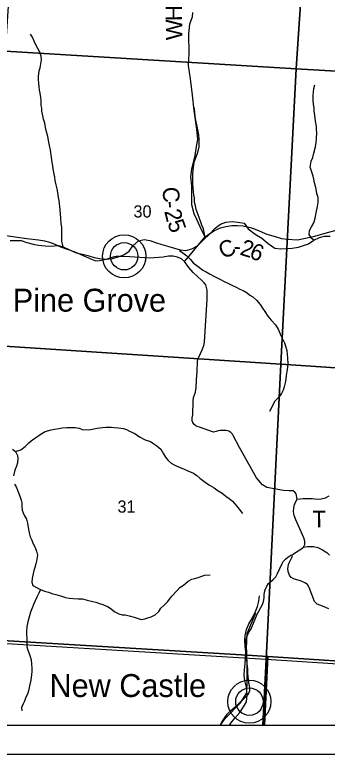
# Model space of a CAD drawing. Extents: x 0 to 34, y 0 to 22.
# Drawn here: x 6.352 to 7.429, y 14 to 16.547 of the extents above; entities that cross this region are included whole.
import ezdxf

# ---------------------------------------------------------------- set-up
doc = ezdxf.new("R2010")
doc.units = 0
for name, color, linetype in [('GM_X_County_Road', 7, 'Continuous'), ('GM_X_County_Road_Text', 7, 'Continuous'), ('GM_X_Minor_River', 7, 'Continuous'), ('GM_X_Rail_Line', 7, 'Continuous'), ('GM_X_Section', 7, 'Continuous'), ('GM_X_Section_Text', 7, 'Continuous'), ('GM_X_State_Route', 7, 'Continuous'), ('GM_X_Township_Road', 7, 'Continuous'), ('GM_X_Township_Road_Text', 7, 'Continuous'), ('GM_X_Unincorporated', 7, 'Continuous'), ('GM_X_Unincorporated_Location', 7, 'Continuous'), ('GM_X_Unincorporated_Text', 7, 'Continuous'), ('SH_Cut_Line', 7, 'Continuous'), ('SH_Data', 7, 'Continuous')]:
    doc.layers.add(name, color=color, linetype=linetype)

msp = doc.modelspace()

# ---------------------------------------------------------------- linework, layer by layer
at = {"layer": 'GM_X_County_Road'}
for points in [[(7.0019, 15.7742), (7.0087, 15.7819), (6.9968, 15.8044), (6.9804, 15.8419), (6.9711, 15.8614), (6.963, 15.8929), (6.963, 15.9563), (6.9594, 15.989), (6.963, 16.0159), (6.9743, 16.0626), (6.9791, 16.0937), (6.9834, 16.118), (6.9795, 16.1533), (6.9708, 16.2175), (6.9647, 16.2703), (6.9586, 16.3266), (6.9517, 16.3722), (6.9539, 16.4139), (6.9528, 16.4808), (6.9564, 16.5157), (6.9645, 16.5396), (6.9662, 16.5551)], [(7.0087, 15.7819), (7.0219, 15.7915), (7.0407, 15.8036), (7.062, 15.813), (7.0797, 15.8184), (7.1006, 15.821), (7.1207, 15.8216), (7.1397, 15.82), (7.1647, 15.8143), (7.1869, 15.8063), (7.2217, 15.7916), (7.2496, 15.7833), (7.2723, 15.7765), (7.2913, 15.7742), (7.327, 15.7714), (7.3551, 15.7777), (7.3867, 15.7844), (7.4221, 15.7954), (7.4604, 15.8049)], [(6.9379, 15.6975), (6.9532, 15.7152), (6.9743, 15.7414), (6.9959, 15.7673), (7.0019, 15.7742)], [(7.4356, 14.5013), (7.4129, 14.5094), (7.3951, 14.5171), (7.3853, 14.5259), (7.3673, 14.5745), (7.3612, 14.5841), (7.3528, 14.5902), (7.3378, 14.5968), (7.3171, 14.6029), (7.3056, 14.6086), (7.2991, 14.6167), (7.2952, 14.6293), (7.2942, 14.6392), (7.2944, 14.646), (7.2962, 14.654), (7.2999, 14.6614), (7.308, 14.6779), (7.31, 14.6832), (7.3092, 14.6869)]]:
    msp.add_lwpolyline(points, dxfattribs=at)
at = {"layer": 'GM_X_Minor_River'}
for points in [[(6.5192, 15.7482), (6.515, 15.767), (6.5146, 15.7822), (6.5146, 15.7917), (6.515, 15.8015), (6.5142, 15.8152), (6.5127, 15.8265), (6.5108, 15.8478), (6.5101, 15.8599), (6.5089, 15.8758), (6.5052, 15.9077), (6.5036, 15.9172), (6.501, 15.935), (6.498, 15.9475), (6.495, 15.9615), (6.4919, 15.976), (6.4904, 15.9873), (6.4882, 15.9987), (6.4851, 16.0169), (6.4833, 16.0268), (6.4806, 16.045), (6.4787, 16.0575), (6.4765, 16.0711), (6.475, 16.0814), (6.4731, 16.0912), (6.4693, 16.1087), (6.4659, 16.128), (6.461, 16.1489), (6.4583, 16.1591), (6.4561, 16.1735), (6.4515, 16.1876), (6.4485, 16.205), (6.4459, 16.2152), (6.4451, 16.2255), (6.4436, 16.235), (6.4429, 16.2528), (6.4421, 16.2623), (6.4398, 16.2774), (6.438, 16.288), (6.4364, 16.299), (6.4353, 16.3112), (6.4338, 16.3229), (6.4338, 16.3351), (6.4361, 16.354), (6.4395, 16.365), (6.4421, 16.3783), (6.4444, 16.392), (6.4436, 16.4041), (6.4387, 16.4185), (6.4316, 16.431), (6.4236, 16.4462), (6.4191, 16.4568), (6.413, 16.4697), (6.4067, 16.4808)], [(7.3831, 15.771), (7.3768, 15.7766), (7.3674, 15.7899), (7.3689, 15.8043), (7.3749, 15.8164), (7.3833, 15.8308), (7.3882, 15.8471), (7.3912, 15.8646), (7.3957, 15.8866), (7.3988, 15.9002), (7.398, 15.9173), (7.3942, 15.9321), (7.3908, 15.9461), (7.389, 15.9567), (7.3856, 15.9685), (7.3829, 15.9814), (7.381, 15.9909), (7.3704, 16.0227), (7.3742, 16.0428), (7.3795, 16.0553), (7.3837, 16.0701), (7.389, 16.0918), (7.3909, 16.1073), (7.3924, 16.1206), (7.3935, 16.1403), (7.3928, 16.1505), (7.392, 16.1619), (7.3894, 16.1805), (7.3882, 16.1911), (7.3867, 16.201), (7.3849, 16.2161), (7.3841, 16.2268), (7.3818, 16.2397), (7.3811, 16.2518), (7.3815, 16.27), (7.3834, 16.2927), (7.3868, 16.3053)], [(7.0095, 15.7782), (7.0067, 15.7909), (7.0026, 15.8095), (6.9977, 15.8228), (6.9935, 15.8327), (6.9887, 15.8452), (6.9834, 15.8619), (6.9781, 15.8763), (6.9755, 15.8892), (6.9714, 15.9021), (6.9714, 15.9162), (6.9692, 15.9272), (6.9681, 15.9382), (6.967, 15.9503), (6.9659, 15.9651), (6.9659, 15.9799), (6.9663, 15.997), (6.9675, 16.0118), (6.9698, 16.0311), (6.9725, 16.0428), (6.9782, 16.0576), (6.982, 16.0701), (6.9855, 16.0815), (6.9878, 16.0928), (6.9878, 16.1046), (6.9882, 16.1194), (6.9871, 16.1342), (6.98, 16.168), (6.9767, 16.1847), (6.9744, 16.1979), (6.9726, 16.2105), (6.9715, 16.2234), (6.9707, 16.2283)], [(6.3364, 15.7701), (6.3542, 15.7697), (6.3743, 15.7693), (6.3939, 15.7624), (6.4159, 15.7575), (6.4344, 15.754), (6.4575, 15.751), (6.4772, 15.7506), (6.5018, 15.7524), (6.5192, 15.7482), (6.5385, 15.7387), (6.5642, 15.7277), (6.5858, 15.7227), (6.6043, 15.7181), (6.6262, 15.7116), (6.644, 15.7074), (6.6675, 15.7051), (6.6887, 15.7074), (6.7088, 15.7135), (6.7281, 15.7199), (6.7463, 15.7328), (6.7596, 15.7507), (6.7789, 15.7682), (6.799, 15.7731), (6.8179, 15.7696), (6.838, 15.7632), (6.8592, 15.7559), (6.883, 15.7487), (6.9027, 15.7429), (6.922, 15.7372), (6.942, 15.7357), (6.9628, 15.7414), (6.9825, 15.7509), (7.0027, 15.7714), (7.0232, 15.7919), (7.0429, 15.8124), (7.0618, 15.8261), (7.08, 15.8333), (7.1016, 15.8355), (7.1209, 15.8329), (7.1432, 15.8294), (7.1564, 15.8093), (7.1806, 15.791), (7.2041, 15.778), (7.2264, 15.7598), (7.2487, 15.7434), (7.268, 15.7407), (7.288, 15.7422), (7.3085, 15.743), (7.3301, 15.7464), (7.3482, 15.7521), (7.3653, 15.7585), (7.3831, 15.771), (7.4028, 15.7805), (7.4203, 15.7851), (7.4392, 15.7851)], [(6.922, 15.7372), (6.9198, 15.7357), (6.9323, 15.7274), (6.9455, 15.7164), (6.958, 15.7039), (6.9678, 15.6925), (6.9848, 15.68), (7.0007, 15.6679), (7.012, 15.6618), (7.0264, 15.6535), (7.0404, 15.6459), (7.0589, 15.6365), (7.0763, 15.627), (7.0869, 15.6224), (7.1001, 15.6156), (7.1152, 15.6088), (7.1277, 15.6016), (7.1398, 15.5971), (7.153, 15.5891), (7.1628, 15.5815), (7.173, 15.5758), (7.1855, 15.5637), (7.198, 15.5493), (7.2059, 15.5368), (7.2146, 15.5247), (7.2252, 15.5095), (7.2361, 15.4947), (7.2516, 15.4788), (7.2607, 15.4644), (7.2709, 15.4401), (7.2773, 15.4261), (7.2826, 15.4166), (7.2864, 15.4018), (7.2902, 15.3905), (7.2913, 15.3768), (7.2928, 15.3654), (7.2936, 15.3453), (7.2921, 15.3328), (7.2905, 15.3184), (7.2875, 15.304), (7.2868, 15.2919), (7.2845, 15.2797), (7.2811, 15.2653), (7.2777, 15.2543), (7.2724, 15.2422), (7.2625, 15.2304), (7.2489, 15.2167), (7.23, 15.1805)], [(6.3549, 15.0422), (6.3731, 15.0487), (6.3886, 15.0604), (6.4014, 15.0726), (6.4146, 15.0836), (6.4271, 15.0927), (6.4396, 15.101), (6.4574, 15.1113), (6.4782, 15.1177), (6.4899, 15.1193), (6.5039, 15.1223), (6.5156, 15.1242), (6.5322, 15.1257), (6.5609, 15.1257), (6.5745, 15.1227), (6.5844, 15.1182), (6.6074, 15.117), (6.6192, 15.1193), (6.6369, 15.1231), (6.6543, 15.125), (6.6664, 15.1269), (6.6857, 15.1266), (6.6963, 15.1258), (6.7095, 15.1243), (6.7276, 15.1224), (6.7378, 15.1186), (6.7477, 15.1133), (6.7666, 15.1042), (6.7824, 15.0936), (6.8017, 15.0834), (6.8206, 15.0769), (6.8312, 15.0697), (6.8422, 15.0622), (6.8554, 15.0508), (6.8648, 15.0352), (6.8724, 15.0235), (6.8811, 15.0121), (6.8913, 15.003), (6.9015, 14.997), (6.9189, 14.989), (6.9344, 14.9826), (6.9491, 14.9765), (6.9684, 14.9678), (6.9797, 14.9606), (6.9907, 14.9507), (7.0088, 14.9367), (7.0236, 14.9265), (7.0398, 14.9181), (7.0534, 14.9075), (7.067, 14.8988), (7.0795, 14.8893), (7.0912, 14.881), (7.103, 14.8715), (7.1169, 14.8552), (7.1264, 14.8446), (7.1377, 14.8295)], [(6.3443, 15.0505), (6.3549, 15.0422), (6.3617, 15.0286), (6.3625, 15.0187), (6.3617, 15.0039), (6.3583, 14.9925), (6.353, 14.9781), (6.3477, 14.9591)], [(6.3515, 14.9307), (6.3583, 14.9186), (6.3613, 14.9091), (6.3662, 14.8981), (6.3704, 14.8852), (6.3749, 14.8753), (6.3768, 14.8655), (6.3772, 14.8537), (6.3779, 14.8412), (6.3813, 14.8314), (6.3855, 14.8207), (6.3923, 14.8094), (6.3968, 14.7953), (6.398, 14.7805), (6.4021, 14.7627), (6.4059, 14.7483), (6.4115, 14.7377), (6.4153, 14.7244), (6.4221, 14.7146), (6.4274, 14.6998), (6.4312, 14.6854), (6.4278, 14.6653), (6.4255, 14.6558), (6.421, 14.6436), (6.4176, 14.6323), (6.4149, 14.6163), (6.4119, 14.6049), (6.4115, 14.5932), (6.4149, 14.5811), (6.43, 14.5727), (6.4406, 14.567), (6.4554, 14.5614), (6.4682, 14.5579), (6.4833, 14.553), (6.4935, 14.5504), (6.5105, 14.5454), (6.5268, 14.5401), (6.5397, 14.5379), (6.554, 14.5364), (6.5706, 14.5356), (6.5858, 14.5349), (6.602, 14.5311), (6.6217, 14.5262), (6.6323, 14.5239), (6.644, 14.5197), (6.6557, 14.5159), (6.6716, 14.5084), (6.6848, 14.5008), (6.6973, 14.4905), (6.7116, 14.4833), (6.723, 14.4803), (6.7332, 14.4796), (6.7472, 14.4762), (6.7638, 14.4716), (6.7774, 14.4678), (6.7891, 14.4644), (6.8005, 14.4659)], [(6.8005, 14.4659), (6.8114, 14.4701), (6.8224, 14.4732), (6.8368, 14.4804), (6.8485, 14.4918), (6.856, 14.5031), (6.8674, 14.5138), (6.8783, 14.5251), (6.887, 14.535), (6.8942, 14.5445), (6.912, 14.5642), (6.9214, 14.5741), (6.9339, 14.5828), (6.9506, 14.5961), (6.963, 14.6026), (6.9729, 14.6052), (6.985, 14.609), (6.9967, 14.6136), (7.008, 14.6162), (7.0254, 14.6174)], [(6.4406, 14.567), (6.4395, 14.5655), (6.4357, 14.5549), (6.4289, 14.5405), (6.4168, 14.5162), (6.4134, 14.5067), (6.407, 14.4889), (6.3971, 14.4555), (6.3945, 14.4392), (6.393, 14.4229), (6.3933, 14.4134), (6.3945, 14.3979), (6.3941, 14.3842), (6.3945, 14.3702), (6.3975, 14.3588), (6.402, 14.347), (6.4058, 14.3364), (6.4084, 14.325), (6.4103, 14.3118), (6.4111, 14.2955), (6.4107, 14.2841), (6.4103, 14.2742), (6.408, 14.2552), (6.4046, 14.2405), (6.4024, 14.2298), (6.3993, 14.2181), (6.3959, 14.2063), (6.391, 14.1961), (6.3861, 14.1832), (6.3808, 14.1733), (6.3759, 14.1608), (6.377, 14.1494)], [(7.0927, 14.1), (7.0969, 14.1072), (7.1109, 14.1243), (7.128, 14.1441), (7.1409, 14.1627), (7.1515, 14.1802), (7.1531, 14.2041), (7.1513, 14.2308), (7.1453, 14.2536), (7.1434, 14.2711), (7.1446, 14.2912), (7.1465, 14.3118), (7.1481, 14.3327), (7.1493, 14.3525), (7.1463, 14.3719), (7.146, 14.3913), (7.1464, 14.4088), (7.151, 14.4293), (7.1594, 14.4494), (7.1723, 14.47), (7.1822, 14.4916), (7.1886, 14.5091), (7.1936, 14.5277), (7.1959, 14.5456)]]:
    msp.add_lwpolyline(points, dxfattribs=at)
at = {"layer": 'GM_X_Rail_Line'}
msp.add_lwpolyline([(7.0621, 14.1), (7.0777, 14.123), (7.1304, 14.177), (7.1522, 14.2117), (7.1532, 14.2534), (7.1539, 14.3132), (7.1513, 14.3637), (7.1532, 14.4153), (7.1836, 14.4865)], dxfattribs=at)
at = {"layer": 'GM_X_Section'}
for points in [[(6.388, 17.4386), (7.3907, 17.3751), (7.3221, 16.3607), (6.3205, 16.4222)], [(7.3907, 17.3751), (8.3983, 17.3128), (8.3308, 16.3019), (7.3221, 16.3607)], [(6.3205, 16.4222), (7.3221, 16.3607), (7.27, 15.3432), (6.2624, 15.4089)], [(7.3221, 16.3607), (8.3308, 16.3019), (8.2829, 15.2756), (7.27, 15.3432)], [(7.27, 15.3432), (7.2187, 14.3265), (6.2103, 14.3869), (6.2624, 15.4089)], [(8.2829, 15.2756), (8.2289, 14.2604), (7.2187, 14.3265), (7.27, 15.3432)]]:
    msp.add_lwpolyline(points, close=True, dxfattribs=at)
at = {"layer": 'GM_X_State_Route'}
for points in [[(6.9379, 15.6975), (6.9273, 15.706), (6.9129, 15.7125), (6.8985, 15.7153), (6.8821, 15.7156), (6.8637, 15.7122), (6.8177, 15.7093), (6.749, 15.7139), (6.7119, 15.715), (6.7015, 15.7145), (6.6905, 15.7121), (6.6794, 15.7092), (6.6674, 15.7046), (6.6517, 15.7004), (6.6376, 15.6988), (6.6294, 15.6998), (6.6178, 15.7041), (6.5812, 15.7207), (6.5608, 15.729), (6.5112, 15.7464), (6.4917, 15.7556), (6.4735, 15.763), (6.4559, 15.7673), (6.4337, 15.7709), (6.3934, 15.7755), (6.354, 15.7806), (6.3131, 15.7863)], [(7.3092, 14.6869), (7.3202, 14.6953), (7.3388, 14.7065), (7.3482, 14.7132), (7.3518, 14.7226), (7.3518, 14.7341), (7.3489, 14.7452), (7.3211, 14.8079), (7.3153, 14.8219), (7.3134, 14.8355), (7.314, 14.8476), (7.316, 14.8564), (7.3203, 14.8683), (7.3257, 14.8782), (7.3224, 14.8968), (7.3183, 14.9022), (7.3122, 14.9069), (7.2977, 14.9069), (7.2788, 14.9079), (7.2218, 14.9189), (7.2062, 14.9283), (7.1861, 14.9518), (7.1276, 15.0567), (7.105, 15.0983), (7.103, 15.1027), (7.0967, 15.1086), (7.09, 15.1129), (7.0806, 15.1153), (7.0694, 15.1153), (7.0607, 15.1149), (7.0541, 15.1137), (7.0472, 15.1111), (7.0377, 15.1098), (6.989, 15.1264), (6.9817, 15.1285), (6.9765, 15.1313), (6.9712, 15.1356), (6.9666, 15.1422), (6.9643, 15.1489), (6.9643, 15.1584), (6.9661, 15.1695), (6.9668, 15.2164), (6.968, 15.2292), (6.9754, 15.2477), (6.9781, 15.2636), (6.9792, 15.2902), (6.981, 15.3187), (6.9824, 15.3527), (6.9837, 15.3605), (6.9867, 15.3677), (6.9983, 15.393), (7.0045, 15.4079), (7.0067, 15.4193), (7.0159, 15.5678), (7.0151, 15.5986), (7.0136, 15.6079), (7.0109, 15.6168), (7.0055, 15.6234), (6.9974, 15.632), (6.9677, 15.6593), (6.9526, 15.6768), (6.9379, 15.6975)], [(7.0607, 14.1), (7.0666, 14.1108), (7.0845, 14.1376), (7.0958, 14.1489), (7.1226, 14.1723), (7.1435, 14.1919), (7.1559, 14.2049), (7.1607, 14.2125), (7.1628, 14.2193), (7.1624, 14.2297), (7.1589, 14.2469), (7.1566, 14.2671), (7.1561, 14.279), (7.1555, 14.2941), (7.1535, 14.3112), (7.1522, 14.3249), (7.1528, 14.3407), (7.1529, 14.3438), (7.1524, 14.3567), (7.1489, 14.3758), (7.1475, 14.3845), (7.1484, 14.3921), (7.1532, 14.4068), (7.1576, 14.4177), (7.1676, 14.4323), (7.1885, 14.4821), (7.2062, 14.5155), (7.2101, 14.5255), (7.212, 14.5385), (7.2122, 14.5479), (7.2137, 14.5586), (7.2159, 14.5661), (7.2212, 14.5786), (7.227, 14.5878), (7.2339, 14.594), (7.2429, 14.6013), (7.2519, 14.6109), (7.258, 14.6226), (7.2666, 14.6396), (7.2741, 14.6564), (7.2781, 14.6639), (7.2861, 14.6723), (7.2934, 14.6787), (7.3036, 14.6861), (7.3092, 14.6869)]]:
    msp.add_lwpolyline(points, dxfattribs=at)
at = {"layer": 'GM_X_Township_Road'}
for points in [[(7.3257, 14.8782), (7.346, 14.8806), (7.3781, 14.8806), (7.3959, 14.8787), (7.4083, 14.8794), (7.4232, 14.8827), (7.4367, 14.8905)], [(7.3482, 14.7132), (7.3618, 14.7157), (7.3821, 14.7159), (7.3976, 14.7117), (7.413, 14.7042), (7.4285, 14.6943), (7.4379, 14.6862)]]:
    msp.add_lwpolyline(points, dxfattribs=at)
at = {"layer": 'GM_X_Township_Road_Text'}
for points in [[(6.1957, 14.1), (7.2077, 14.1), (7.2187, 14.3265), (6.2103, 14.3869)], [(7.2077, 14.1), (8.2148, 14.1), (8.2289, 14.2604), (7.2187, 14.3265)]]:
    msp.add_lwpolyline(points, close=True, dxfattribs=at)
at = {"layer": 'GM_X_Unincorporated'}
msp.add_lwpolyline([(4.0882, 16.6114), (4.2937, 16.1161), (4.4847, 15.685), (4.802, 14.9692), (4.3998, 14.7897), (4.2904, 14.7408), (3.8099, 14.5285), (4.1531, 14.503), (4.2897, 14.5063), (4.438, 14.498), (6.2131, 14.3976), (7.1526, 14.3412), (7.2248, 14.3369), (7.5073, 14.3182), (7.991, 14.2863), (8.4238, 14.2578), (8.9, 14.2264), (8.9, 20.3234)], dxfattribs=at)
for points in [[(2.8399, 14.1), (7.2132, 14.1), (7.2248, 14.3369), (7.1526, 14.3412), (6.2131, 14.3976), (4.438, 14.498), (4.2897, 14.5063), (4.1531, 14.503), (3.8099, 14.5285), (2.9778, 14.1609)], [(7.2132, 14.1), (8.9, 14.1), (8.9, 14.2264), (8.4238, 14.2578), (7.991, 14.2863), (7.5073, 14.3182), (7.2248, 14.3369)]]:
    msp.add_lwpolyline(points, close=True, dxfattribs=at)
for centre, radius in [((6.7296, 15.7152), 0.0744), ((6.7296, 15.7152), 0.0472), ((7.1611, 14.181), 0.0744), ((7.1611, 14.181), 0.0472)]:
    msp.add_circle(centre, radius, dxfattribs=at)
at = {"layer": 'GM_X_Unincorporated_Location'}
for p, q in [((6.7296, 15.7152), (6.7296, 15.7152)), ((7.1611, 14.181), (7.1611, 14.181))]:
    msp.add_line(p, q, dxfattribs=at)
at = {"layer": 'SH_Cut_Line'}
msp.add_lwpolyline([(4.0882, 16.6114), (4.2937, 16.1161), (4.4847, 15.685), (4.802, 14.9692), (4.3998, 14.7897), (4.2904, 14.7408), (3.8099, 14.5285), (2.9778, 14.1609), (2.8399, 14.1), (8.9, 14.1), (8.9, 20.9)], dxfattribs=at)
at = {"layer": 'SH_Data'}
for p, q in [((2.1, 14.1), (8.9, 14.1)), ((2, 14), (9, 14))]:
    msp.add_line(p, q, dxfattribs=at)

# ---------------------------------------------------------------- texts
at = {"layer": 'GM_X_County_Road_Text'}
for s, rotation, p in [('H', 90.8561, (6.9295, 16.5259)), ('W', 90.8632, (6.9305, 16.4601)), ('C', 271.7566, (6.8625, 15.9536)), ('-', 274.1186, (6.8641, 15.9044)), ('2', 283.9778, (6.8674, 15.8706)), ('5', 289.514, (6.8776, 15.8309)), ('C', 23.8061, (7.0701, 15.7049)), ('2', 342.1468, (7.1254, 15.7217)), ('-', 356.485, (7.1058, 15.7225)), ('6', 337.8005, (7.1577, 15.7114))]:
    msp.add_text(s, height=0.0568, rotation=rotation, dxfattribs=at).set_placement(p)
at = {"layer": 'GM_X_Section_Text'}
for s, p in [('30', (6.7616, 15.8488)), ('31', (6.7066, 14.8321))]:
    msp.add_text(s, height=0.04186, rotation=0, dxfattribs=at).set_placement(p)
at = {"layer": 'GM_X_Township_Road_Text'}
msp.add_text('T', height=0.0568, rotation=0.2829, dxfattribs=at).set_placement((7.3786, 14.7818))
at = {"layer": 'GM_X_Unincorporated_Text'}
for s, p in [('Pine Grove', (6.3454, 15.5245)), ('New Castle', (6.472, 14.197))]:
    msp.add_text(s, height=0.07898, rotation=0, dxfattribs=at).set_placement(p)

doc.saveas('drawing.dxf')
